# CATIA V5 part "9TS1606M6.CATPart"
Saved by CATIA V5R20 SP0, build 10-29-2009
Part number: 9TS1606M6
Revision: ANY
Definition: UNKNOWN
Nomenclature: 9TS1606M6
Source: Unknown
Bounding box of the stored display mesh (mm): x -8 to 8, y -8 to 8, z 0 to 6
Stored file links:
  C:\Users\Utente\Desktop\IO LAVORO\3D X SITO CF\CUMSA\3D files GR\GR 222826-10\9TS1606M6.CATPart
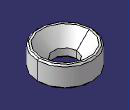
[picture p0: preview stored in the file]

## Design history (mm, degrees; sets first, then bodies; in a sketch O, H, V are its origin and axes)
Body1 "Chaflán1" (main body)
  Solid1: solid without history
